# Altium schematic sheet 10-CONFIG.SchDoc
size A4
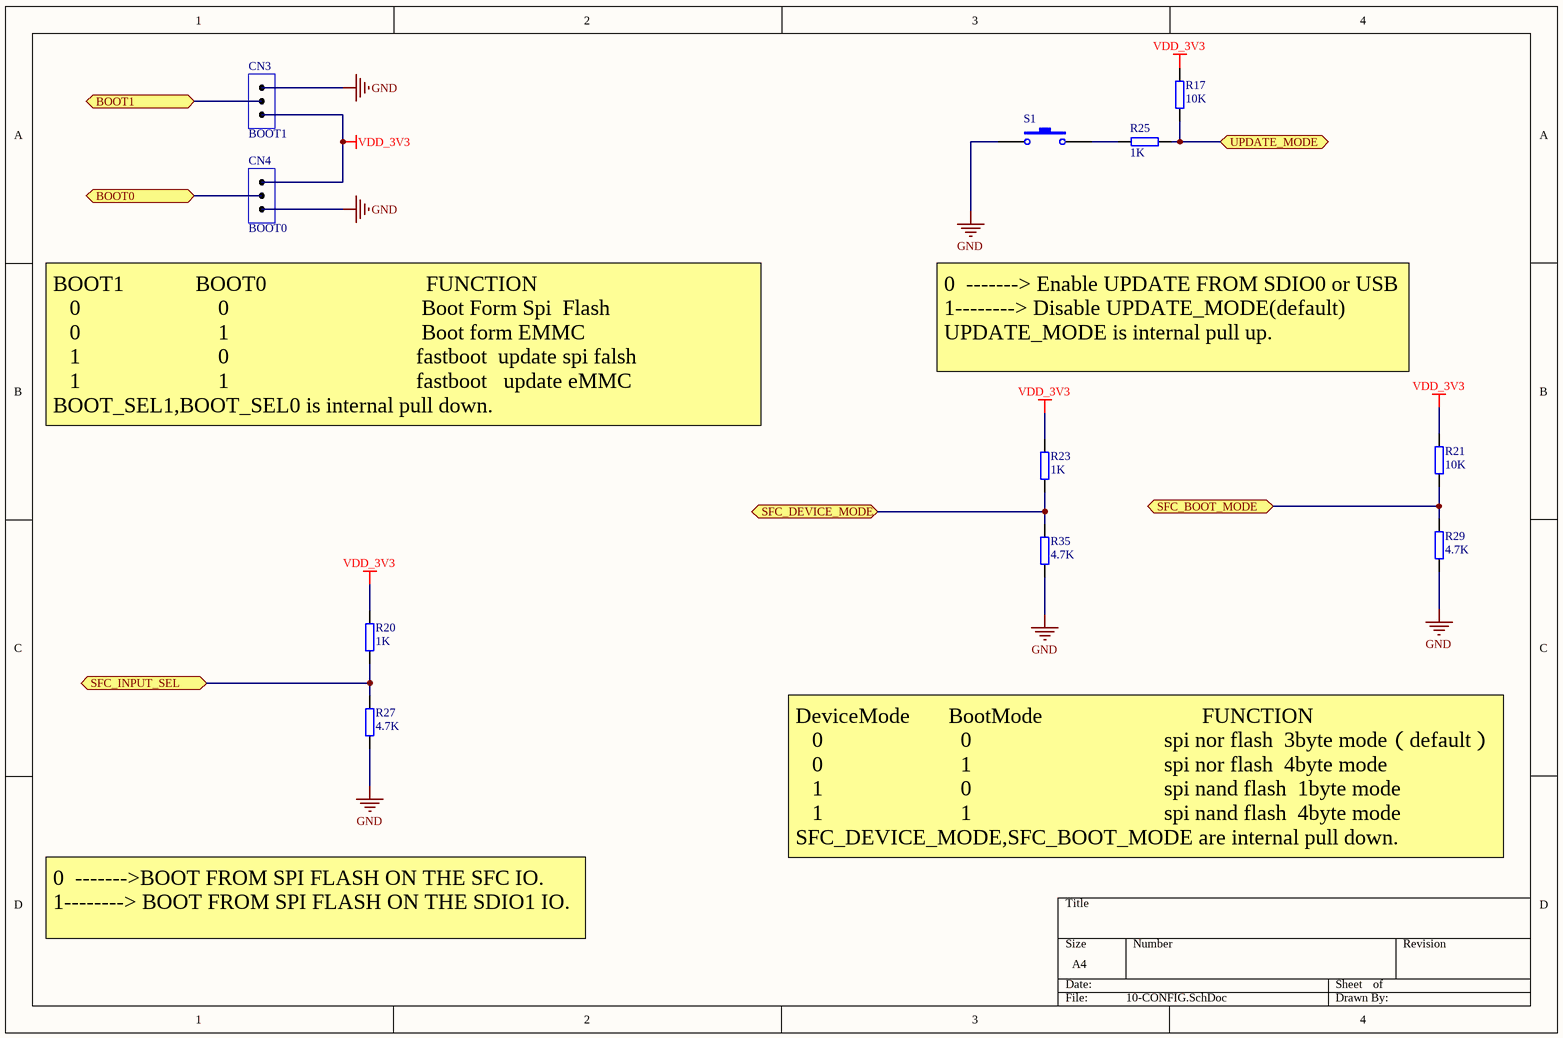
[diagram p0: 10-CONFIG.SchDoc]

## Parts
CN3  BOOT1  [SIP3(1.27_SMD)]
CN4  BOOT0  [SIP3(1.27_SMD)]
R17  10K  [R0402]
R20  1K  [R0402]
R21  10K  [R0402]
R23  1K  [R0402]
R25  1K  [R0402]
R27  4.7K  [R0402]
R29  4.7K  [R0402]
R35  4.7K  [R0402]
S1  SW-PB  [KEY(3.2*4.2)]  (value not drawn)

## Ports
BOOT0 (bidir), BOOT1 (bidir), SFC_BOOT_MODE (bidir), SFC_DEVICE_MODE (bidir), SFC_INPUT_SEL (bidir), UPDATE_MODE (bidir)

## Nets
GND: CN3.1 CN4.3 R27.2 R29.2 R35.2 S1.1
VDD_3V3: CN3.3 CN4.1 R17.1 R20.1 R21.1 R23.1
BOOT0: CN4.2 ; port BOOT0
BOOT1: CN3.2 ; port BOOT1
SFC_BOOT_MODE: R21.2 R29.1 ; port SFC_BOOT_MODE
SFC_DEVICE_MODE: R23.2 R35.1 ; port SFC_DEVICE_MODE
SFC_INPUT_SEL: R20.2 R27.1 ; port SFC_INPUT_SEL
UPDATE_MODE: R17.2 R25.2 ; port UPDATE_MODE
NetR25_1: R25.1 S1.2

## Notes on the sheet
- 0  -------> Enable UPDATE FROM SDIO0 or USB
  1--------> Disable UPDATE_MODE(default)
  UPDATE_MODE is internal pull up.
- BOOT1             BOOT0                             FUNCTION
  0                         0                                   Boot Form Spi  Flash
  0                         1                                   Boot form EMMC
  1                         0                                  fastboot  update spi falsh
  1                         1                                  fastboot   update eMMC
  BOOT_SEL1,BOOT_SEL0 is internal pull down.
- DeviceMode       BootMode                             FUNCTION
  0                         0                                   spi nor flash  3byte mode（default）
  0                         1                                   spi nor flash  4byte mode
  1                         0                                   spi nand flash  1byte mode
  1                         1                                   spi nand flash  4byte mode
  SFC_DEVICE_MODE,SFC_BOOT_MODE are internal pull down.
- 0  ------->BOOT FROM SPI FLASH ON THE SFC IO.
  1--------> BOOT FROM SPI FLASH ON THE SDIO1 IO.

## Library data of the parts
CN3 CN4 = CN-3
R17 R20 R21 R23 R25 R27 R29 R35 = 电阻Ω: Resistor
S1 = SW-PB: Switch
